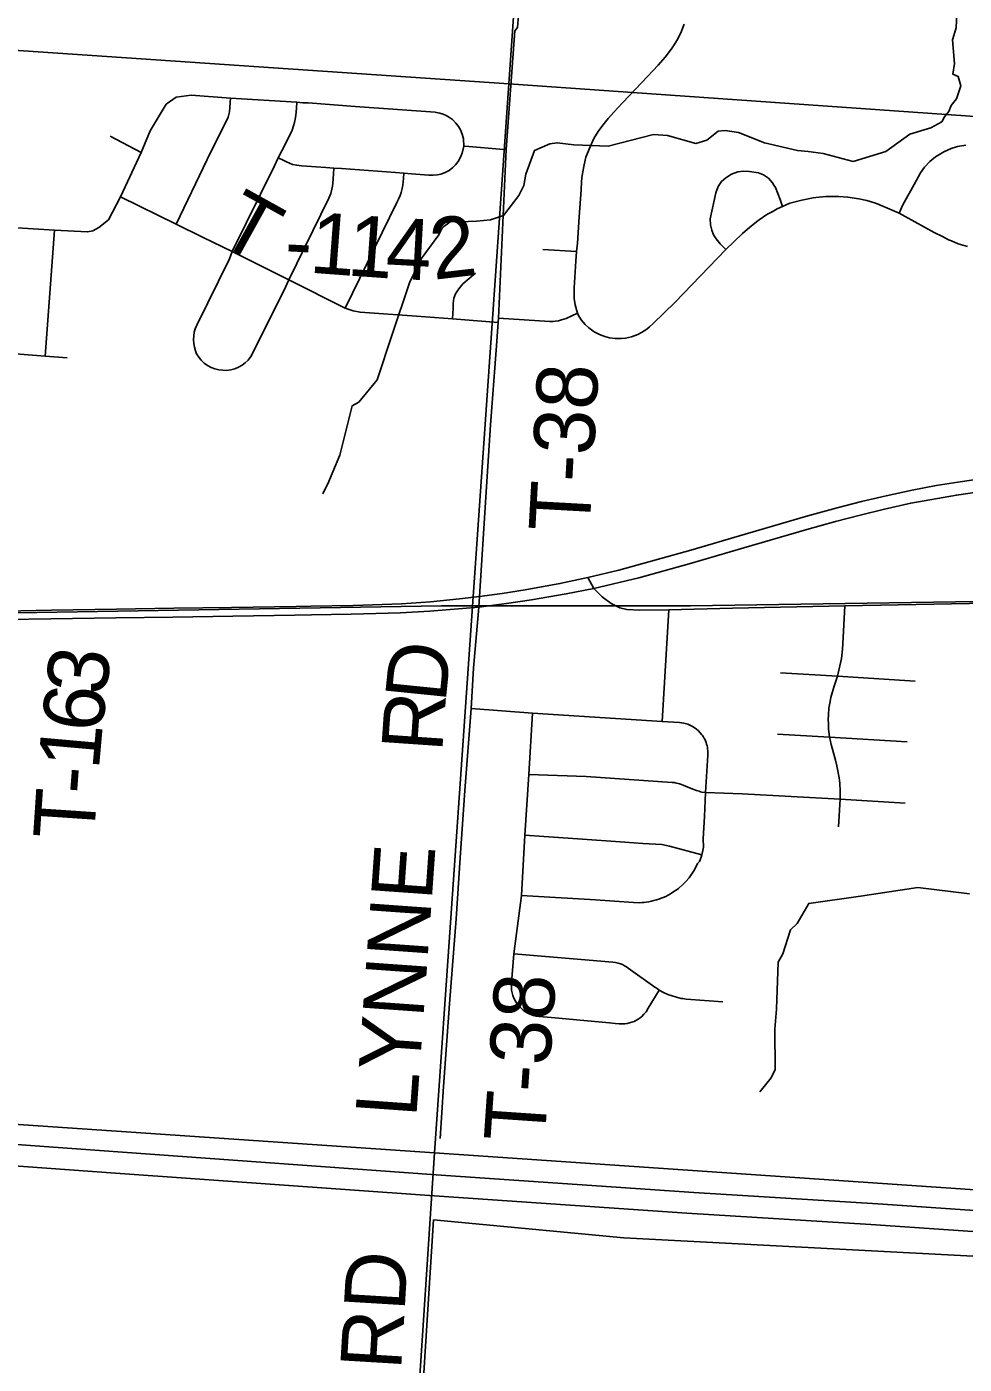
# Model space of a CAD drawing. Extents: x 0 to 34, y 0 to 22.
# Drawn here: x 4.778 to 5.651, y 16.537 to 17.784 of the extents above; entities that cross this region are included whole.
import ezdxf

# ---------------------------------------------------------------- set-up
doc = ezdxf.new("R2010")
doc.units = 0
for name, color, linetype in [('GM_X_Interstate_Route', 7, 'Continuous'), ('GM_X_Minor_River', 7, 'Continuous'), ('GM_X_Rail_Line', 7, 'Continuous'), ('GM_X_Section', 7, 'Continuous'), ('GM_X_Township_Road', 7, 'Continuous'), ('GM_X_Township_Road_Text', 7, 'Continuous'), ('GM_X_US_Route', 7, 'Continuous')]:
    doc.layers.add(name, color=color, linetype=linetype)

msp = doc.modelspace()

# ---------------------------------------------------------------- linework, layer by layer
at = {"layer": 'GM_X_Interstate_Route'}
for points in [[(3.3501, 16.8435), (3.6568, 16.822), (3.9185, 16.8032), (4.14, 16.7877), (4.3722, 16.7712), (4.604, 16.7548), (4.6996, 16.7473), (4.8669, 16.7351), (5.1594, 16.714), (5.3993, 16.6976), (5.5708, 16.6871), (5.7197, 16.6768), (5.8676, 16.668), (5.8733, 16.6677), (6.0223, 16.6571), (6.2793, 16.6405), (6.5008, 16.6267), (6.5803, 16.6216)], [(3.3497, 16.8226), (3.6565, 16.8011), (3.9181, 16.7823), (4.1396, 16.7667), (4.3718, 16.7503), (4.6036, 16.7339), (4.693, 16.7276), (4.8604, 16.7157), (5.1529, 16.6946), (5.3928, 16.6782), (5.5644, 16.6677), (5.7091, 16.6577), (5.7188, 16.6572), (5.8539, 16.6483)]]:
    msp.add_lwpolyline(points, dxfattribs=at)
at = {"layer": 'GM_X_Minor_River'}
for points in [[(5.6445, 17.7964), (5.6437, 17.7827), (5.6403, 17.7717), (5.6422, 17.7497), (5.6406, 17.7398), (5.6455, 17.7376), (5.6482, 17.7288), (5.644, 17.7167), (5.639, 17.7106), (5.6371, 17.7049), (5.633, 17.7), (5.6303, 17.6951), (5.6201, 17.6898), (5.6007, 17.6838), (5.5784, 17.6675), (5.5477, 17.6584), (5.52, 17.6657), (5.506, 17.6676), (5.4958, 17.6684), (5.4652, 17.6757), (5.4409, 17.6853), (5.4285, 17.6872), (5.422, 17.6864)], [(5.422, 17.6864), (5.4114, 17.6781), (5.4012, 17.6751), (5.3747, 17.6824), (5.3618, 17.6835), (5.3194, 17.6726), (5.2876, 17.6738), (5.272, 17.6758), (5.2652, 17.6746), (5.2508, 17.6686), (5.2428, 17.6466), (5.2409, 17.636), (5.2363, 17.6265), (5.2219, 17.6079), (5.2098, 17.6038), (5.1969, 17.6027), (5.189, 17.6023), (5.1723, 17.602), (5.1651, 17.5967), (5.1617, 17.5899), (5.1453, 17.5675), (5.1343, 17.5451), (5.1183, 17.497), (5.1042, 17.4549), (5.0871, 17.434), (5.0811, 17.4306), (5.0696, 17.3847), (5.0631, 17.3692), (5.0593, 17.3601), (5.0536, 17.3487)], [(5.6561, 16.976), (5.608, 16.9819), (5.5546, 16.9736), (5.5065, 16.9669), (5.4955, 16.9483), (5.4894, 16.9423), (5.4822, 16.9199), (5.478, 16.9123), (5.4764, 16.8683), (5.4748, 16.8497), (5.4751, 16.8121), (5.4713, 16.8045), (5.4607, 16.7912)]]:
    msp.add_lwpolyline(points, dxfattribs=at)
at = {"layer": 'GM_X_Rail_Line'}
msp.add_lwpolyline([(2.1, 17.1885), (2.293, 17.1932), (3.2433, 17.211), (3.5049, 17.2168), (5.1641, 17.2441), (5.3961, 17.2441), (6.3843, 17.2591), (6.7484, 17.272), (7.243, 17.2836), (8.0477, 17.3015), (8.4974, 17.3184), (8.9, 17.3324)], dxfattribs=at)
at = {"layer": 'GM_X_Section'}
for points in [[(4.2612, 18.3613), (4.4567, 18.3488), (4.4602, 18.3486), (4.9805, 18.3133), (5.2662, 18.2926), (5.2271, 17.7305), (4.7425, 17.7636), (4.2214, 17.7996)], [(5.2662, 18.2926), (5.3729, 18.2854), (5.6268, 18.2675), (6.2624, 18.2212), (6.2291, 17.6617), (5.7501, 17.6941), (5.2271, 17.7305)], [(4.7425, 17.7636), (5.2271, 17.7305), (5.1577, 16.7346), (4.6741, 16.7675)], [(5.2271, 17.7305), (5.7501, 17.6941), (5.6796, 16.6989), (5.1577, 16.7346)], [(4.6741, 16.7675), (5.1577, 16.7346), (5.0919, 15.7328), (4.5921, 15.7668)], [(5.1577, 16.7346), (5.6796, 16.6989), (5.6042, 15.6994), (5.0919, 15.7328)]]:
    msp.add_lwpolyline(points, close=True, dxfattribs=at)
at = {"layer": 'GM_X_Township_Road'}
for p, q in [((4.8554, 17.6818), (4.8843, 17.6667)), ((4.7949, 17.477), (4.8035, 17.5944)), ((5.2899, 17.5745), (5.2587, 17.5764)), ((5.3699, 17.1364), (5.3762, 17.2404)), ((5.4801, 17.1817), (5.5333, 17.1786)), ((5.5333, 17.1786), (5.6057, 17.174)), ((5.4772, 17.1247), (5.5259, 17.1219)), ((5.5259, 17.1219), (5.5981, 17.1174))]:
    msp.add_line(p, q, dxfattribs=at)
for points in [[(5.1991, 17.243), (5.1996, 17.2528), (5.2054, 17.3455), (5.21, 17.413), (5.2152, 17.4824), (5.2171, 17.5084), (5.2172, 17.5123), (5.2246, 17.6696), (5.2326, 17.78), (5.2351, 17.7833), (5.2368, 17.8055), (5.2368, 17.8139), (5.2401, 17.865), (5.2392, 17.8706), (5.2531, 18.0362), (5.2612, 18.1878), (5.2684, 18.2947)], [(5.3903, 17.7864), (5.3873, 17.7782), (5.3835, 17.7711), (5.381, 17.7671), (5.3786, 17.7632), (5.3727, 17.7555), (5.3661, 17.7481), (5.351, 17.7318), (5.3329, 17.713), (5.3247, 17.7043), (5.3194, 17.6985), (5.3145, 17.692), (5.3102, 17.6862), (5.3062, 17.6796), (5.3026, 17.6718), (5.2988, 17.6622), (5.2971, 17.6553), (5.2956, 17.6472), (5.2951, 17.6432), (5.2947, 17.6393), (5.2945, 17.632), (5.2926, 17.6067), (5.291, 17.5821), (5.2899, 17.5745), (5.2894, 17.5653), (5.2879, 17.5407), (5.2877, 17.5346), (5.2879, 17.5306), (5.2889, 17.5248), (5.2908, 17.517), (5.292, 17.5147), (5.2944, 17.5108), (5.2981, 17.5065), (5.3016, 17.5032), (5.3065, 17.4997), (5.3113, 17.497), (5.3163, 17.4951), (5.3207, 17.494), (5.3261, 17.4933), (5.3321, 17.4932), (5.3357, 17.4936), (5.3414, 17.4949), (5.3472, 17.4971), (5.3505, 17.4988), (5.3556, 17.5021), (5.3579, 17.5041), (5.361, 17.5071), (5.3821, 17.5273), (5.4293, 17.5762), (5.4367, 17.5834), (5.4447, 17.5912), (5.4515, 17.5972), (5.459, 17.6029), (5.4602, 17.6039), (5.4674, 17.6089), (5.4723, 17.6115), (5.4771, 17.6142), (5.4821, 17.6163), (5.4888, 17.6193), (5.5001, 17.6223), (5.5105, 17.6243), (5.5131, 17.6246), (5.5222, 17.6256), (5.5277, 17.6258), (5.5344, 17.6256), (5.5428, 17.625), (5.553, 17.6235), (5.5604, 17.6219), (5.5637, 17.6209), (5.5697, 17.619), (5.5842, 17.613), (5.5907, 17.6102), (5.5964, 17.607), (5.6234, 17.592), (5.6312, 17.5883), (5.6366, 17.5853), (5.6393, 17.5843), (5.6458, 17.5817), (5.6545, 17.579)], [(4.7688, 17.5964), (4.8035, 17.5944), (4.8344, 17.5926), (4.8392, 17.5936), (4.8449, 17.5967), (4.8539, 17.6038), (4.865, 17.6253), (4.8843, 17.6667), (4.8929, 17.6867), (4.9076, 17.7116), (4.917, 17.7183), (4.9309, 17.7202), (4.9677, 17.7172), (5.0294, 17.7135), (5.0351, 17.7131), (5.0399, 17.7129), (5.0837, 17.7096), (5.1582, 17.7041), (5.1609, 17.7037), (5.1626, 17.7033), (5.1657, 17.7023), (5.1686, 17.7011), (5.1717, 17.6993), (5.1744, 17.6973), (5.1776, 17.694), (5.18, 17.691), (5.1819, 17.6877), (5.1834, 17.6836), (5.1846, 17.6793), (5.185, 17.6726), (5.1898, 17.6723), (5.2185, 17.6699), (5.2246, 17.6696)], [(4.9169, 17.5998), (4.9459, 17.6601), (4.9655, 17.6995), (4.9668, 17.7046), (4.9677, 17.7172)], [(4.9691, 17.5744), (5.0087, 17.6543), (5.0121, 17.6618), (5.0154, 17.6682), (5.0234, 17.6842), (5.025, 17.6876), (5.0263, 17.6915), (5.0273, 17.6947), (5.0279, 17.6976), (5.0284, 17.701), (5.0287, 17.7046), (5.0291, 17.708), (5.0294, 17.7135)], [(5.0121, 17.6618), (5.0168, 17.6594), (5.0198, 17.6579), (5.0225, 17.6568), (5.0255, 17.6556), (5.0294, 17.6548), (5.0338, 17.6543), (5.0384, 17.654), (5.0565, 17.6527), (5.0639, 17.6521), (5.0711, 17.6516), (5.1215, 17.6479), (5.1291, 17.6473), (5.1364, 17.6468), (5.1524, 17.6456), (5.1565, 17.6455), (5.1604, 17.6458), (5.1637, 17.6466), (5.1675, 17.648), (5.1713, 17.6499), (5.1748, 17.6527), (5.1774, 17.6553), (5.1797, 17.6584), (5.182, 17.6623), (5.1835, 17.666), (5.185, 17.6726)], [(5.5907, 17.6102), (5.594, 17.618), (5.6046, 17.6368), (5.6106, 17.6477), (5.6144, 17.6531), (5.6192, 17.6584), (5.6244, 17.6625), (5.6322, 17.6673), (5.6392, 17.6703), (5.6451, 17.6723), (5.6527, 17.6734)], [(5.0219, 17.548), (5.0591, 17.6241), (5.0612, 17.6285), (5.0621, 17.6324), (5.0627, 17.6354), (5.063, 17.638), (5.0635, 17.6464), (5.0639, 17.6521)], [(5.4293, 17.5762), (5.424, 17.5817), (5.4203, 17.5861), (5.4178, 17.5899), (5.416, 17.5944), (5.4148, 17.5992), (5.4147, 17.6048), (5.42, 17.629), (5.422, 17.6349), (5.425, 17.6395), (5.4292, 17.6432), (5.4344, 17.6465), (5.4404, 17.6488), (5.4457, 17.6494), (5.4512, 17.6491), (5.4595, 17.6477), (5.4642, 17.646), (5.4689, 17.6428), (5.4726, 17.6385), (5.474, 17.6363), (5.4754, 17.6341), (5.4798, 17.623), (5.4821, 17.6163)], [(5.0744, 17.5217), (5.1227, 17.62), (5.1243, 17.6233), (5.1258, 17.6267), (5.1267, 17.6294), (5.1277, 17.633), (5.1282, 17.6363), (5.1287, 17.6424), (5.1291, 17.6473)], [(4.865, 17.6253), (4.9169, 17.5998), (4.9422, 17.5876), (4.9691, 17.5744), (5.0219, 17.548), (5.0744, 17.5217), (5.0818, 17.519), (5.0883, 17.5178), (5.1409, 17.5141)], [(4.9691, 17.5744), (4.9666, 17.5675), (4.9362, 17.5057), (4.9348, 17.5025), (4.9338, 17.4992), (4.9333, 17.4957), (4.9331, 17.4923), (4.9334, 17.4888), (4.934, 17.4854), (4.9351, 17.482), (4.936, 17.4792), (4.938, 17.476), (4.9404, 17.4731), (4.9431, 17.4705), (4.9462, 17.4682), (4.9495, 17.4664), (4.953, 17.4651), (4.9567, 17.4642), (4.9604, 17.4637), (4.964, 17.4636), (4.9679, 17.464), (4.9716, 17.465), (4.9751, 17.4665), (4.9784, 17.4684), (4.9814, 17.4707), (4.9842, 17.4733), (4.9867, 17.4767), (4.9885, 17.4799), (5.019, 17.5413), (5.0219, 17.548)], [(5.1745, 17.5117), (5.175, 17.5217), (5.1752, 17.5259), (5.1758, 17.5308), (5.1773, 17.5349), (5.1804, 17.5397), (5.1841, 17.5442), (5.1958, 17.5543)], [(5.1409, 17.5141), (5.1745, 17.5117), (5.2171, 17.5084)], [(5.2172, 17.5123), (5.2653, 17.5093), (5.2683, 17.5093), (5.2706, 17.5094), (5.2733, 17.5098), (5.276, 17.5106), (5.2803, 17.5119), (5.2857, 17.5144), (5.2908, 17.517)], [(4.8154, 17.4754), (4.7949, 17.477), (4.7596, 17.4797)], [(5.3005, 17.2706), (5.3062, 17.2604), (5.3138, 17.2526), (5.3224, 17.2465), (5.3303, 17.2424), (5.3369, 17.2408), (5.3489, 17.2401), (5.3762, 17.2404), (5.4353, 17.2421), (5.5401, 17.2442), (5.6726, 17.2466), (5.7376, 17.2477), (5.7699, 17.2481), (5.8045, 17.2488), (5.8374, 17.2499), (5.8697, 17.2499), (5.9017, 17.2507), (5.9355, 17.252), (5.9679, 17.2528), (6.002, 17.2534), (6.0347, 17.2538), (6.068, 17.2541), (6.1266, 17.255), (6.2346, 17.257)], [(5.1631, 16.7479), (5.1661, 16.7963), (5.1718, 16.8732), (5.1778, 16.9526), (5.1817, 17.0095), (5.186, 17.0722), (5.1919, 17.1487), (5.1941, 17.1862), (5.1991, 17.243)], [(5.5401, 17.2442), (5.5386, 17.2147), (5.538, 17.2038), (5.5369, 17.1952), (5.5333, 17.1786), (5.5301, 17.1693), (5.5281, 17.1631), (5.527, 17.1588), (5.526, 17.1535), (5.5252, 17.1489), (5.5247, 17.1427), (5.5245, 17.1379), (5.5247, 17.1347), (5.5249, 17.1296), (5.5259, 17.1219), (5.5265, 17.1194), (5.5274, 17.115), (5.5312, 17.1005), (5.5326, 17.095), (5.5349, 17.084), (5.5354, 17.0789), (5.5357, 17.0716), (5.5356, 17.0641), (5.534, 17.0384)], [(5.1919, 17.1487), (5.2491, 17.1443), (5.3699, 17.1364), (5.386, 17.1354), (5.3879, 17.1352), (5.3899, 17.1348), (5.3925, 17.1342), (5.3938, 17.1338), (5.395, 17.1333), (5.3968, 17.1324), (5.3982, 17.1317), (5.3998, 17.1307), (5.4017, 17.1293), (5.4036, 17.1278), (5.4065, 17.1244), (5.4074, 17.1234), (5.408, 17.1224), (5.4087, 17.1213), (5.4095, 17.1199), (5.4102, 17.1183), (5.4107, 17.117), (5.4112, 17.1154), (5.4117, 17.1139), (5.412, 17.1125), (5.4122, 17.1109), (5.4124, 17.109), (5.4125, 17.1072), (5.4124, 17.1051), (5.4103, 17.0703), (5.4092, 17.0478), (5.4079, 17.0271), (5.4082, 17.0192), (5.4076, 17.0162), (5.4067, 17.0123), (5.4061, 17.0099), (5.4047, 17.006), (5.4028, 17.0041), (5.4012, 17.0008), (5.3993, 16.9972), (5.3976, 16.9945), (5.395, 16.9909), (5.3918, 16.9873), (5.3891, 16.9845), (5.3851, 16.9808), (5.3829, 16.9792), (5.3808, 16.9779), (5.3776, 16.9759), (5.3733, 16.9735), (5.3709, 16.9725), (5.3688, 16.9717), (5.3667, 16.9708), (5.3647, 16.9702), (5.3622, 16.9695), (5.3598, 16.969), (5.3573, 16.9685), (5.3549, 16.9681), (5.3531, 16.9679), (5.3509, 16.9677), (5.349, 16.9676), (5.3431, 16.9677), (5.3078, 16.9701), (5.2387, 16.9743)], [(5.236, 16.8717), (5.2345, 16.8736), (5.2331, 16.8758), (5.2315, 16.8787), (5.2306, 16.8811), (5.23, 16.8837), (5.2295, 16.8862), (5.2293, 16.8887), (5.2294, 16.8906), (5.2295, 16.8929), (5.2316, 16.9199), (5.2387, 16.9743), (5.2419, 17.0304), (5.2455, 17.0871), (5.2491, 17.1443)], [(5.2455, 17.0871), (5.299, 17.0852), (5.3793, 17.0796), (5.381, 17.0795), (5.3821, 17.0793), (5.3832, 17.0791), (5.3846, 17.0788), (5.386, 17.0784), (5.3878, 17.0778), (5.3917, 17.0761), (5.3984, 17.0735), (5.4017, 17.0722), (5.4043, 17.0714), (5.4057, 17.071), (5.4069, 17.0707), (5.4103, 17.0703), (5.4444, 17.0691), (5.5356, 17.0641), (5.5963, 17.0604)], [(5.2419, 17.0304), (5.2597, 17.0292), (5.2913, 17.0271), (5.3349, 17.0239), (5.3517, 17.0229), (5.3694, 17.0217), (5.3767, 17.0202), (5.4067, 17.0123)], [(5.2316, 16.9199), (5.3238, 16.9121), (5.3263, 16.9119), (5.3287, 16.9113), (5.3309, 16.9106), (5.3328, 16.9099), (5.3348, 16.9088), (5.3367, 16.9078), (5.3382, 16.9067), (5.3629, 16.889), (5.3651, 16.8875), (5.3671, 16.8862), (5.371, 16.884), (5.3752, 16.8821), (5.3791, 16.8807), (5.3833, 16.8794), (5.3876, 16.8784), (5.3891, 16.8782), (5.3921, 16.8778), (5.4263, 16.8751)], [(5.236, 16.8717), (5.2403, 16.8674), (5.242, 16.8661), (5.244, 16.8649), (5.2466, 16.8637), (5.2495, 16.8626), (5.2523, 16.8618), (5.2552, 16.8614), (5.27, 16.8602), (5.2933, 16.858), (5.3209, 16.8555), (5.3262, 16.855), (5.3299, 16.8548), (5.3326, 16.8547), (5.3351, 16.8548), (5.3373, 16.8551), (5.3395, 16.8556), (5.3417, 16.8562), (5.3436, 16.857), (5.3453, 16.8577), (5.3476, 16.8591), (5.3494, 16.8603), (5.351, 16.8615), (5.3528, 16.8636), (5.3548, 16.866), (5.3569, 16.8693), (5.3671, 16.8862)], [(5.1107, 15.9789), (5.1444, 16.4755), (5.1567, 16.672)], [(5.1567, 16.672), (5.3341, 16.6553), (5.6597, 16.6381), (5.7163, 16.6266), (5.7354, 16.6205), (5.7461, 16.6148), (5.7517, 16.6083), (5.7574, 16.6007), (5.7604, 16.5964), (5.7768, 16.5599), (5.7828, 16.5516), (5.7881, 16.5461), (5.8118, 16.524), (5.8355, 16.5045), (5.8491, 16.4956), (5.8559, 16.4925), (5.8608, 16.4909), (5.8689, 16.4902), (5.8764, 16.4915), (5.8935, 16.497)]]:
    msp.add_lwpolyline(points, dxfattribs=at)
at = {"layer": 'GM_X_US_Route'}
for points in [[(5.0426, 17.2438), (5.082, 17.2445), (5.1269, 17.2461), (5.1539, 17.248), (5.1811, 17.2506), (5.1996, 17.2528), (5.2207, 17.2556), (5.2422, 17.2592), (5.2745, 17.265), (5.3005, 17.2706), (5.3294, 17.2774), (5.3519, 17.2836), (5.3965, 17.2962), (5.4471, 17.3109), (5.5057, 17.328), (5.5328, 17.3356), (5.5555, 17.3413), (5.5786, 17.3468), (5.6028, 17.3521), (5.6252, 17.3563), (5.6454, 17.3595), (5.6729, 17.3635)], [(5.3062, 17.2604), (5.3482, 17.2703), (5.3951, 17.2835), (5.4458, 17.2982), (5.5046, 17.3153), (5.5313, 17.3228), (5.5542, 17.3287), (5.5771, 17.3342), (5.6014, 17.34), (5.644, 17.3474), (5.6715, 17.3514), (5.6934, 17.3543), (5.7094, 17.3559), (5.7355, 17.3585), (5.7699, 17.3602), (5.8101, 17.3613), (5.8697, 17.3623)], [(5.0431, 17.2358), (5.0801, 17.2363), (5.1261, 17.2376), (5.1535, 17.2391), (5.1991, 17.243), (5.2248, 17.2463), (5.248, 17.2499), (5.2804, 17.2553), (5.3062, 17.2604)], [(4.7579, 17.2393), (4.8008, 17.2401), (4.8613, 17.241), (4.9148, 17.2419), (4.9686, 17.2428), (5.0288, 17.2436), (5.0426, 17.2438)], [(4.7589, 17.2316), (4.8003, 17.232), (4.8608, 17.2331), (4.9138, 17.2338), (4.9699, 17.2346), (5.0275, 17.2355), (5.0431, 17.2358)]]:
    msp.add_lwpolyline(points, dxfattribs=at)

# ---------------------------------------------------------------- texts
at = {"layer": 'GM_X_Township_Road_Text'}
for s, height, rotation, p in [('T', 0.0568, 330.9887, (4.9532, 17.5843)), ('1', 0.0568, 355.64, (5.0403, 17.5548)), ('1', 0.0568, 355.8766, (5.0754, 17.5522)), ('4', 0.0568, 356.875, (5.1114, 17.5496)), ('2', 0.0568, 6.6516, (5.1569, 17.548)), ('-', 0.0568, 357.1196, (5.0173, 17.556)), ('T-38', 0.05682, 86.8206, (5.3021, 17.3122)), ('3', 0.0568, 83.4546, (4.8517, 17.16)), ('D', 0.0568, 84.231, (5.168, 17.1533)), ('6', 0.0568, 83.9834, (4.848, 17.1253)), ('R', 0.0568, 86.0431, (5.1648, 17.1072)), ('1', 0.0568, 84.8932, (4.8449, 17.0907)), ('-', 0.0568, 85.6947, (4.8432, 17.0676)), ('T', 0.0568, 86.1614, (4.8403, 17.0253)), ('LYNNE', 0.05682, 85.9295, (5.1407, 16.7668)), ('T-38', 0.05682, 86.091, (5.2603, 16.7435)), ('RD', 0.05682, 86.5467, (5.1265, 16.5315))]:
    msp.add_text(s, height=height, rotation=rotation, dxfattribs=at).set_placement(p)

doc.saveas('drawing.dxf')
